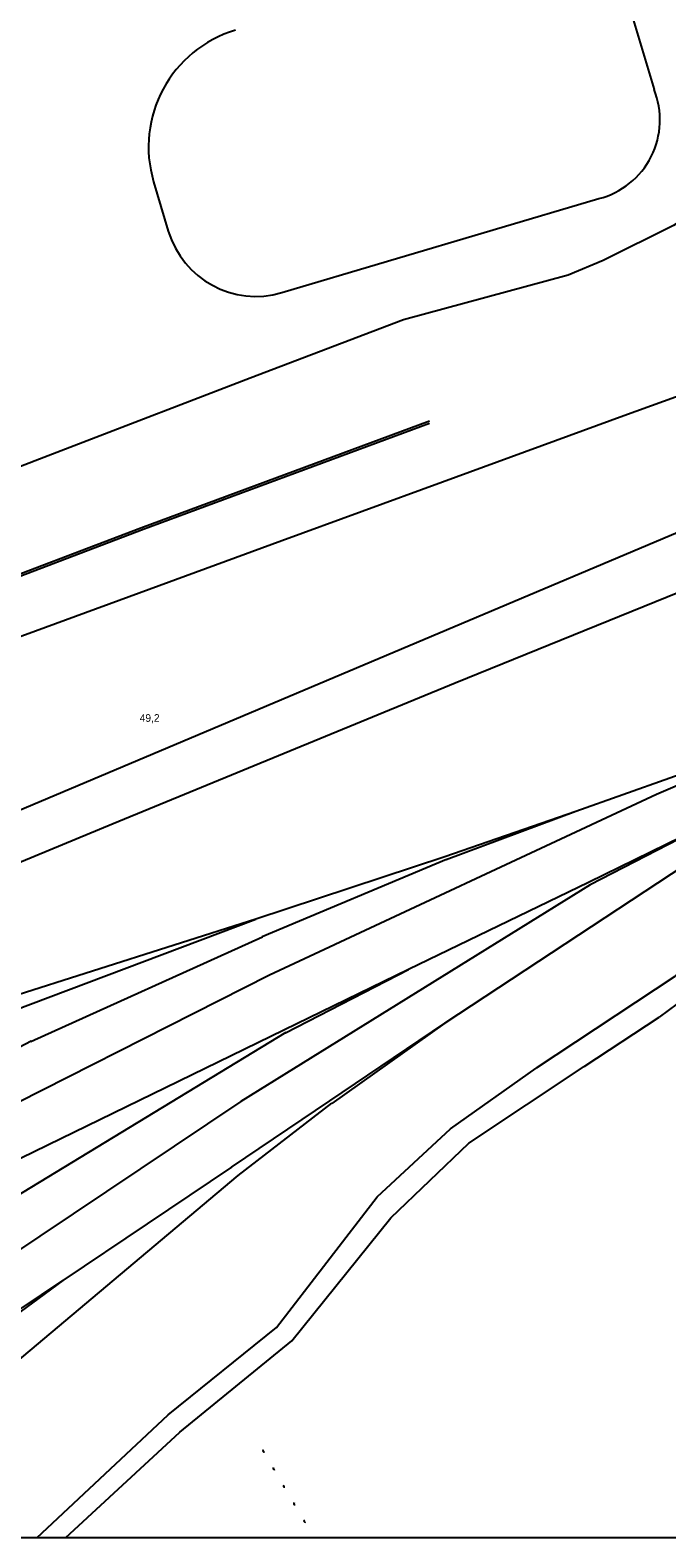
# Model space of a CAD drawing. Extents: x -932734 to -932083, y -737151 to -736752.
# Drawn here: x -932480.24 to -932473.97, y -736822.8 to -736807.96 of the extents above; entities that cross this region are included whole.
import ezdxf

# ---------------------------------------------------------------- set-up
doc = ezdxf.new("R2010")
doc.units = 0
for name, color, linetype in [('BorderBW', 7, 'Continuous'), ('Objekty_stávající', 7, 'Continuous'), ('SL_24_VODOVOD_PITNA', 7, 'Continuous'), ('WA_34_SCHODISTE', 7, 'Continuous'), ('WA_46_TEXT', 7, 'Continuous')]:
    doc.layers.add(name, color=color, linetype=linetype)

# ---------------------------------------------------------------- blocks, each defined once
blk = doc.blocks.new('GPLO225')
blk.add_arc((0, 0), 0.00025, 0, 180)
blk = doc.blocks.new('přehledka_1')
at = {"layer": 'BorderBW'}
for points in [[(0.07882806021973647, -0.043247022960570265), (0.07314789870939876, -0.04535205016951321), (0.06976789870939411, -0.04664005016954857), (0.06998951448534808, -0.047241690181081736)], [(0.07882806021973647, -0.043289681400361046), (0.07316197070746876, -0.04538949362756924), (0.06981910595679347, -0.04666334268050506), (0.07002704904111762, -0.04722786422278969)]]:
    blk.add_lwpolyline(points, dxfattribs=at)
at = {"layer": 'Objekty_stávající'}
for points in [[(0.07021389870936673, -0.04768805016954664), (0.0731158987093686, -0.04662405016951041), (0.0759258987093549, -0.045598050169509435), (0.0790858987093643, -0.044442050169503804), (0.0826538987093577, -0.043138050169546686), (0.08506789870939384, -0.04226005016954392), (0.0883658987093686, -0.04105005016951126), (0.0913138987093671, -0.03997405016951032), (0.09556989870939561, -0.03842205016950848), (0.0984598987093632, -0.03735805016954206), (0.09991516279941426, -0.036821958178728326)], [(0.03445734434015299, -0.06521838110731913), (0.036093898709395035, -0.06463005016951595), (0.04202189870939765, -0.06243405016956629), (0.0462318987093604, -0.06083805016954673), (0.053853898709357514, -0.05786005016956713), (0.057567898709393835, -0.05638005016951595), (0.06646389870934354, -0.05271205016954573), (0.07220389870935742, -0.050292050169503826), (0.07886789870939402, -0.04748005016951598), (0.0843098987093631, -0.045184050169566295), (0.08998389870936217, -0.042780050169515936), (0.0970738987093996, -0.03980405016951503), (0.09991516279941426, -0.03862719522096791)], [(0.03707951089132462, -0.06521838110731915), (0.0423098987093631, -0.06328005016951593), (0.0465698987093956, -0.06166605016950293), (0.05413589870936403, -0.05872005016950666), (0.06680589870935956, -0.053566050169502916), (0.07260589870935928, -0.05116405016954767), (0.0793358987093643, -0.04839405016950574), (0.08490189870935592, -0.04613605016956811), (0.09028589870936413, -0.044012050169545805), (0.0972998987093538, -0.041326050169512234), (0.09991516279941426, -0.0403290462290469)], [(0.08797569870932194, -0.04868965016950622), (0.08543629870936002, -0.04967485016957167), (0.0833004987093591, -0.05059485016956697), (0.07568049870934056, -0.05414905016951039), (0.06922669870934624, -0.05741405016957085)], [(0.08908329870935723, -0.04884865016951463), (0.08797369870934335, -0.049455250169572), (0.08594689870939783, -0.05060845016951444), (0.07913269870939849, -0.055093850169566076)], [(0.0879726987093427, -0.04869085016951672), (0.08541029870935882, -0.04961705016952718), (0.08171189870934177, -0.05092925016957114)], [(0.08171189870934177, -0.05092925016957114), (0.07913269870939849, -0.05182165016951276)], [(0.08171189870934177, -0.05092925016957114), (0.07915769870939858, -0.05187645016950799)], [(0.08440069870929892, -0.05113105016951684), (0.08195849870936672, -0.05232105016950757), (0.07841649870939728, -0.05403305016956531), (0.07596669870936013, -0.055228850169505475), (0.07054209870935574, -0.057871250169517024), (0.06574909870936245, -0.06052825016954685), (0.05903593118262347, -0.06521838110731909)], [(0.08440069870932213, -0.05113105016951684), (0.08199049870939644, -0.052367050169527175), (0.0751196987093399, -0.056634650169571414), (0.06719969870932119, -0.06193325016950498)], [(0.07913069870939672, -0.051822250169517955), (0.07541009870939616, -0.05304845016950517), (0.07058929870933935, -0.054578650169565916)], [(0.0791632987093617, -0.051874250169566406), (0.07553729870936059, -0.05339225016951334)], [(0.0532065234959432, -0.06521838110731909), (0.06063189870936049, -0.06015325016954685), (0.06605249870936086, -0.05692725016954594), (0.07063089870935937, -0.05484865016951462), (0.07541009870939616, -0.05304845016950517)], [(0.05320652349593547, -0.0652183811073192), (0.06063189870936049, -0.06015325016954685), (0.06605249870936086, -0.05692725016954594), (0.07063089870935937, -0.05484865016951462), (0.07541009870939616, -0.05304845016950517)], [(0.05320652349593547, -0.0652183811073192), (0.06063189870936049, -0.06015325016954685), (0.06605249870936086, -0.05692725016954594), (0.07063089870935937, -0.05484865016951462), (0.07541009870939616, -0.05304845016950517)], [(0.07098709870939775, -0.05545265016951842), (0.07554109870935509, -0.05339065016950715)], [(0.07599769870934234, -0.05528145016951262), (0.07841649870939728, -0.054033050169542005)], [(0.07493189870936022, -0.05792305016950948), (0.07687209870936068, -0.05661705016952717), (0.07913269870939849, -0.055093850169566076)], [(0.07913269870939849, -0.055093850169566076), (0.07690689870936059, -0.05667105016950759)], [(0.07099469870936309, -0.05544885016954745), (0.0652186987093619, -0.058488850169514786), (0.05557305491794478, -0.06521838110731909)], [(0.07600629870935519, -0.055276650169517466), (0.07016849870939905, -0.05881525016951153), (0.06478249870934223, -0.06234985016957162)], [(0.07001209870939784, -0.06233385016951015), (0.0750636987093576, -0.05808785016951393), (0.07691129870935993, -0.05666765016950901)], [(0.07493189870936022, -0.05792305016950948), (0.07161789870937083, -0.06015305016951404)], [(0.06420773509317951, -0.06521838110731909), (0.0674128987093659, -0.06297625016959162), (0.07161789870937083, -0.06015305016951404)], [(0.07161789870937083, -0.06015305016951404), (0.0675508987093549, -0.06314165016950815)]]:
    blk.add_lwpolyline(points, dxfattribs=at)
at = {"layer": 'SL_24_VODOVOD_PITNA'}
for p, q in [((0.08046743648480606, -0.02740511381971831), (0.08325050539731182, -0.03672147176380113)), ((0.0734022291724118, -0.038539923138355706), (0.07369089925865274, -0.03950620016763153)), ((0.07592679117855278, -0.04071684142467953), (0.08216567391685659, -0.03886887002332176))]:
    blk.add_line(p, q, dxfattribs=at)
for centre, radius, start, end in [((0.07570180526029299, -0.037852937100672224), 0.0024000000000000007, 106.64695426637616, 196.63323198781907), ((0.08176645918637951, -0.03731947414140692), 0.0016, 284.44847135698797, 21.947170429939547), ((0.0754155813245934, -0.0389909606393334), 0.0018000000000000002, 196.63323198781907, 286.4994135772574)]:
    blk.add_arc(centre, radius, start, end, dxfattribs=at)
at = {"layer": 'WA_34_SCHODISTE'}
blk.add_lwpolyline([(0, 0), (0.09991516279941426, 0), (0.09991516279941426, -0.06521838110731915), (0, -0.06521838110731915)], close=True, dxfattribs=at)
at = {"layer": 'WA_46_TEXT'}
for points in [[(0.08627789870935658, -0.037758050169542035), (0.08363389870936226, -0.039394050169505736), (0.08224789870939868, -0.040084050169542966), (0.08155850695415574, -0.04037674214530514), (0.07831989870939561, -0.0412500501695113), (0.07529989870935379, -0.042404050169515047), (0.07174989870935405, -0.04376805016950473), (0.06721389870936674, -0.04551005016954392), (0.06387989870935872, -0.04677005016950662), (0.06302782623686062, -0.04706505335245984), (0.06120989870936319, -0.04773405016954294), (0.05674789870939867, -0.04935205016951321), (0.05208789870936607, -0.051014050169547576), (0.04977189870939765, -0.05189805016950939), (0.04848589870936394, -0.052330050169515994), (0.04734589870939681, -0.05270005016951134), (0.04302789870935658, -0.05413205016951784), (0.03886189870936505, -0.05539005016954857), (0.03673589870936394, -0.05607005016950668), (0.03664486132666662, -0.05610461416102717)], [(0.08515589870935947, -0.05271005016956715), (0.08461989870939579, -0.05310605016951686), (0.08365989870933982, -0.05417605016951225), (0.08092789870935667, -0.0559760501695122)], [(0.08544189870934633, -0.053284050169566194), (0.08480989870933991, -0.05374205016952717), (0.08388389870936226, -0.05458205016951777), (0.08334789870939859, -0.05497405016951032)], [(0.07960389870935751, -0.05745005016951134), (0.08187389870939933, -0.05594605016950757), (0.08334789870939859, -0.05497405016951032)], [(0.0777978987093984, -0.05851005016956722), (0.0792458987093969, -0.05717405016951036), (0.08092789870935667, -0.0559760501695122)], [(0.07612389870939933, -0.06134005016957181), (0.07806989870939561, -0.05892005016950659), (0.07960389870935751, -0.05745005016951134)], [(0.07368589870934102, -0.0627960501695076), (0.07581989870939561, -0.06107805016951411), (0.0777978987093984, -0.05851005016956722)], [(0.07166705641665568, -0.06521838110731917), (0.07391989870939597, -0.06314205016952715), (0.07612389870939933, -0.06134005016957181)], [(0.07110577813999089, -0.06521838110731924), (0.07368589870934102, -0.0627960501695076)]]:
    blk.add_lwpolyline(points, dxfattribs=at)
at = {"layer": 'BorderBW', "xscale": 0.08000000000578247, "yscale": 0.08000000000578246, "rotation": 120.31952828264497}
for p in [(0.07557176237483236, -0.06350734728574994), (0.07577369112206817, -0.06385263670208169), (0.07597561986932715, -0.06419792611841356), (0.07617754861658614, -0.064543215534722), (0.07637947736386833, -0.06488850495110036)]:
    blk.add_blockref('GPLO225', p, dxfattribs=at)
at = {"layer": 'Objekty_stávající'}
blk.add_text('49,2', height=0.00015000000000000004, dxfattribs=at).set_placement((0.07312789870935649, -0.049162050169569))

msp = doc.modelspace()

# ---------------------------------------------------------------- block references
at = {"layer": 'SL_24_VODOVOD_PITNA', "xscale": 499.99957, "yscale": 499.99957}
msp.add_blockref('přehledka_1', (-932515.7231447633, -736790.1871344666), dxfattribs=at)

doc.saveas('drawing.dxf')
